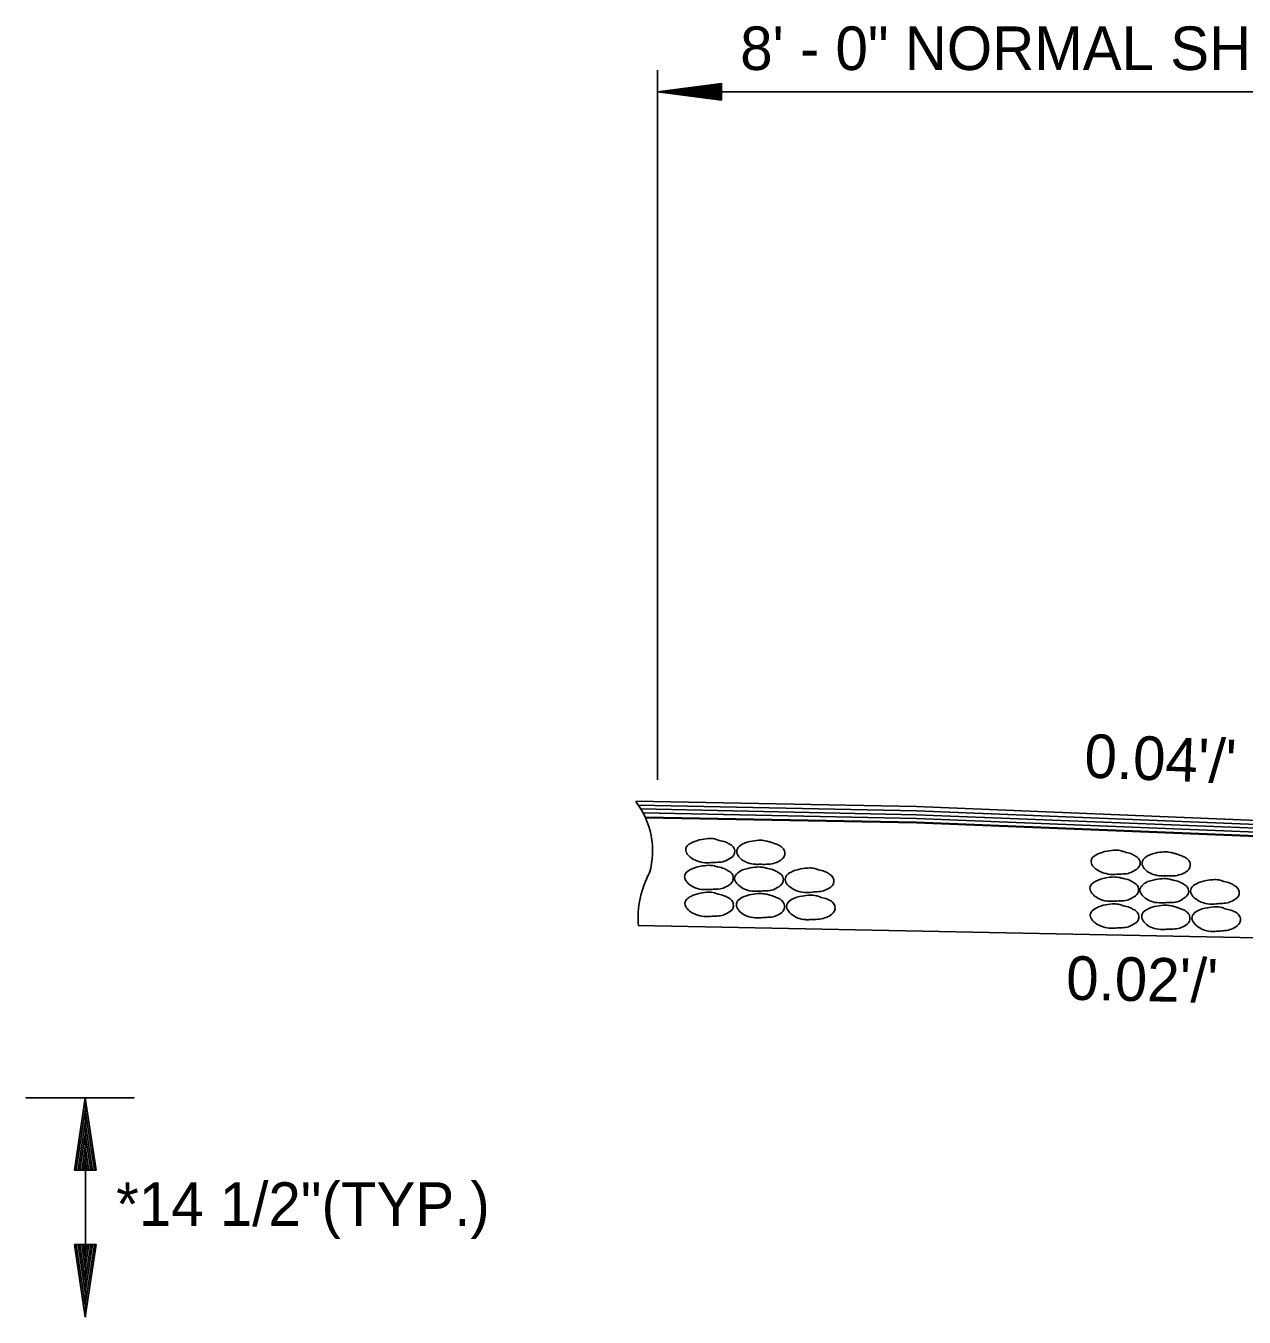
# Model space of a CAD drawing. Extents: x -2842 to 2681, y -2139 to 474.
# Drawn here: x 271.8 to 439.5, y -1517.8 to -1339.9 of the extents above; entities that cross this region are included whole.
import ezdxf

# ---------------------------------------------------------------- set-up
doc = ezdxf.new("R2010")
doc.units = 0
for name, color, linetype in [('BDR_Plan Profile Grid 3', 7, 'Continuous'), ('Default', 7, 'Continuous'), ('R_Border', 7, 'Continuous'), ('R_Border Notes', 7, 'Continuous')]:
    doc.layers.add(name, color=color, linetype=linetype)

msp = doc.modelspace()

# ---------------------------------------------------------------- linework, layer by layer
at = {"layer": 'BDR_Plan Profile Grid 3'}
for p, q in [((355.74, -1446.7), (394.39, -1447.45)), ((356.14, -1447.23), (394.39, -1448.03)), ((501.39, -1451.78), (394.39, -1447.45)), ((356.45, -1447.77), (394.39, -1448.57)), ((356.76, -1448.3), (394.39, -1449.1)), ((357.08, -1448.88), (394.39, -1449.59)), ((357.08, -1448.97), (394.39, -1449.68)), ((501.39, -1452.27), (394.39, -1448.03)), ((501.39, -1452.8), (394.39, -1448.57)), ((501.39, -1453.38), (394.39, -1449.1)), ((501.35, -1453.92), (394.35, -1449.59)), ((501.35, -1453.96), (394.39, -1449.68)), ((356.1, -1463.82), (640.63, -1469.52))]:
    msp.add_line(p, q, dxfattribs=at)
for centre, radius, start, end in [((347.05, -1453.52), 11.02, 343.9329, 37.9843), ((368.94, -1462.73), 12.87, 151.4224, 185.1058)]:
    msp.add_arc(centre, radius, start, end, dxfattribs=at)
for points in [[(366.04, -1451.82), (364.83, -1451.96), (363.5, -1452.4), (362.74, -1452.98), (362.65, -1453.43), (362.96, -1454.14), (363.36, -1454.5), (364.17, -1454.9), (365.28, -1455.17), (365.9, -1455.17), (366.8, -1455.12), (367.73, -1455.03), (368.49, -1454.72), (369.25, -1454.1), (369.38, -1453.65), (369.16, -1452.98), (368.62, -1452.58), (368.09, -1452.31), (367.24, -1452.09), (366.75, -1451.91), (366.04, -1451.82)], [(372.95, -1452.05), (371.79, -1452.18), (370.41, -1452.62), (369.74, -1453.25), (369.65, -1453.65), (369.96, -1454.36), (370.32, -1454.72), (371.16, -1455.17), (372.28, -1455.39), (372.86, -1455.39), (373.75, -1455.39), (374.73, -1455.26), (375.49, -1454.94), (376.2, -1454.27), (376.29, -1453.87), (376.07, -1453.25), (375.53, -1452.8), (375, -1452.58), (374.24, -1452.31), (373.71, -1452.18), (372.95, -1452.05)], [(421.86, -1453.43), (420.65, -1453.56), (419.31, -1454.01), (418.56, -1454.59), (418.47, -1455.03), (418.78, -1455.75), (419.18, -1456.1), (419.98, -1456.5), (421.1, -1456.77), (421.72, -1456.77), (422.61, -1456.73), (423.55, -1456.64), (424.31, -1456.33), (425.07, -1455.7), (425.2, -1455.26), (424.98, -1454.59), (424.44, -1454.19), (423.91, -1453.92), (423.06, -1453.69), (422.57, -1453.52), (421.86, -1453.43)], [(428.77, -1453.65), (427.61, -1453.78), (426.23, -1454.23), (425.56, -1454.85), (425.47, -1455.26), (425.78, -1455.97), (426.14, -1456.33), (426.98, -1456.77), (428.1, -1456.99), (428.68, -1456.99), (429.57, -1456.99), (430.55, -1456.86), (431.31, -1456.55), (432.02, -1455.88), (432.11, -1455.48), (431.89, -1454.85), (431.35, -1454.41), (430.82, -1454.19), (430.06, -1453.92), (429.52, -1453.78), (428.77, -1453.65)], [(365.81, -1455.52), (364.66, -1455.66), (363.27, -1456.1), (362.56, -1456.73), (362.47, -1457.08), (362.78, -1457.8), (363.18, -1458.2), (363.94, -1458.64), (365.1, -1458.87), (365.73, -1458.87), (366.62, -1458.82), (367.6, -1458.73), (368.36, -1458.38), (369.07, -1457.75), (369.16, -1457.31), (368.98, -1456.64), (368.4, -1456.24), (367.91, -1455.97), (367.06, -1455.75), (366.57, -1455.61), (365.81, -1455.52)], [(372.68, -1455.75), (371.52, -1455.88), (370.14, -1456.33), (369.47, -1456.95), (369.34, -1457.31), (369.65, -1458.02), (370.09, -1458.42), (370.85, -1458.87), (372.01, -1459.09), (372.59, -1459.09), (373.48, -1459.04), (374.46, -1458.96), (375.22, -1458.6), (375.94, -1457.97), (376.07, -1457.53), (375.85, -1456.86), (375.31, -1456.46), (374.78, -1456.19), (373.93, -1455.97), (373.44, -1455.83), (372.68, -1455.75)], [(379.68, -1455.88), (378.48, -1456.01), (377.14, -1456.46), (376.43, -1457.08), (376.34, -1457.48), (376.65, -1458.2), (377.05, -1458.55), (377.81, -1459), (378.97, -1459.27), (379.59, -1459.27), (380.48, -1459.18), (381.42, -1459.09), (382.18, -1458.78), (382.93, -1458.15), (383.02, -1457.71), (382.8, -1457.08), (382.27, -1456.64), (381.73, -1456.37), (380.93, -1456.15), (380.39, -1455.97), (379.68, -1455.88)], [(421.63, -1457.13), (420.47, -1457.26), (419.09, -1457.71), (418.38, -1458.33), (418.29, -1458.69), (418.6, -1459.4), (419, -1459.8), (419.76, -1460.25), (420.92, -1460.47), (421.54, -1460.47), (422.44, -1460.43), (423.42, -1460.34), (424.17, -1459.98), (424.89, -1459.36), (424.98, -1458.91), (424.8, -1458.24), (424.22, -1457.84), (423.73, -1457.57), (422.88, -1457.35), (422.39, -1457.22), (421.63, -1457.13)], [(428.5, -1457.35), (427.34, -1457.48), (425.96, -1457.93), (425.29, -1458.55), (425.16, -1458.91), (425.47, -1459.62), (425.91, -1460.03), (426.67, -1460.47), (427.83, -1460.69), (428.41, -1460.69), (429.3, -1460.65), (430.28, -1460.56), (431.04, -1460.2), (431.75, -1459.58), (431.89, -1459.13), (431.66, -1458.47), (431.13, -1458.06), (430.59, -1457.8), (429.75, -1457.57), (429.26, -1457.44), (428.5, -1457.35)], [(435.5, -1457.48), (434.29, -1457.62), (432.96, -1458.06), (432.24, -1458.69), (432.15, -1459.09), (432.47, -1459.8), (432.87, -1460.16), (433.63, -1460.61), (434.79, -1460.87), (435.41, -1460.87), (436.3, -1460.78), (437.24, -1460.69), (438, -1460.38), (438.75, -1459.76), (438.84, -1459.31), (438.62, -1458.69), (438.08, -1458.24), (437.55, -1457.97), (436.75, -1457.75), (436.21, -1457.57), (435.5, -1457.48)], [(365.81, -1459.22), (364.66, -1459.36), (363.32, -1459.8), (362.65, -1460.38), (362.52, -1460.83), (362.87, -1461.54), (363.23, -1461.9), (364.03, -1462.3), (365.15, -1462.57), (365.77, -1462.57), (366.66, -1462.52), (367.6, -1462.43), (368.36, -1462.12), (369.11, -1461.5), (369.2, -1461.05), (368.98, -1460.38), (368.45, -1459.98), (367.91, -1459.71), (367.11, -1459.49), (366.57, -1459.31), (365.81, -1459.22)], [(372.9, -1459.4), (371.7, -1459.54), (370.36, -1459.98), (369.69, -1460.56), (369.6, -1461.01), (369.92, -1461.72), (370.27, -1462.08), (371.08, -1462.52), (372.19, -1462.75), (372.81, -1462.75), (373.71, -1462.7), (374.64, -1462.61), (375.44, -1462.3), (376.16, -1461.63), (376.25, -1461.23), (376.02, -1460.56), (375.49, -1460.11), (374.95, -1459.89), (374.2, -1459.62), (373.66, -1459.49), (372.9, -1459.4)], [(379.81, -1459.62), (378.65, -1459.76), (377.27, -1460.2), (376.6, -1460.83), (376.51, -1461.23), (376.83, -1461.9), (377.23, -1462.3), (377.99, -1462.75), (379.15, -1463.01), (379.68, -1463.01), (380.57, -1462.97), (381.55, -1462.83), (382.36, -1462.52), (383.07, -1461.9), (383.2, -1461.41), (382.98, -1460.78), (382.44, -1460.34), (381.86, -1460.11), (381.11, -1459.89), (380.57, -1459.71), (379.81, -1459.62)], [(421.63, -1460.83), (420.47, -1460.96), (419.14, -1461.41), (418.47, -1461.99), (418.33, -1462.43), (418.69, -1463.15), (419.05, -1463.5), (419.85, -1463.9), (420.96, -1464.17), (421.59, -1464.17), (422.48, -1464.13), (423.42, -1464.04), (424.17, -1463.73), (424.93, -1463.1), (425.02, -1462.66), (424.8, -1461.99), (424.26, -1461.59), (423.73, -1461.32), (422.93, -1461.1), (422.39, -1460.92), (421.63, -1460.83)], [(428.72, -1461.01), (427.52, -1461.14), (426.18, -1461.59), (425.51, -1462.17), (425.42, -1462.61), (425.73, -1463.32), (426.09, -1463.68), (426.89, -1464.13), (428.01, -1464.35), (428.63, -1464.35), (429.52, -1464.31), (430.46, -1464.22), (431.26, -1463.9), (431.98, -1463.24), (432.07, -1462.83), (431.84, -1462.17), (431.31, -1461.72), (430.77, -1461.5), (430.01, -1461.23), (429.48, -1461.1), (428.72, -1461.01)], [(435.63, -1461.23), (434.47, -1461.36), (433.09, -1461.81), (432.42, -1462.43), (432.33, -1462.83), (432.65, -1463.5), (433.05, -1463.9), (433.8, -1464.35), (434.96, -1464.62), (435.5, -1464.62), (436.39, -1464.57), (437.37, -1464.44), (438.17, -1464.13), (438.89, -1463.5), (439.02, -1463.01), (438.8, -1462.39), (438.26, -1461.94), (437.68, -1461.72), (436.93, -1461.5), (436.39, -1461.32), (435.63, -1461.23)]]:
    msp.add_spline(points, degree=3, dxfattribs=at)
at = {"layer": 'Default'}
for p, q in [((271.75, -1487.54), (286.69, -1487.54)), ((278.44, -1497.53), (279.94, -1487.53)), ((281.44, -1497.53), (279.94, -1487.53)), ((279.95, -1487.54), (279.95, -1517.75)), ((278.69, -1497.53), (279.94, -1489.18)), ((281.19, -1497.53), (279.94, -1489.18)), ((278.96, -1497.53), (279.94, -1490.9)), ((280.94, -1497.53), (279.94, -1490.9)), ((279.21, -1497.53), (279.94, -1492.58)), ((280.69, -1497.53), (279.94, -1492.58)), ((279.46, -1497.53), (279.94, -1494.28)), ((280.44, -1497.53), (279.94, -1494.28)), ((279.71, -1497.53), (279.94, -1495.93)), ((280.19, -1497.53), (279.94, -1495.93)), ((278.44, -1497.53), (281.44, -1497.53)), ((278.44, -1507.75), (279.94, -1517.75)), ((281.44, -1507.75), (278.44, -1507.75)), ((278.69, -1507.75), (279.94, -1516.08)), ((278.96, -1507.75), (279.94, -1514.35)), ((279.21, -1507.75), (279.94, -1512.7)), ((279.46, -1507.75), (279.94, -1511)), ((279.71, -1507.75), (279.94, -1509.33)), ((281.44, -1507.75), (279.94, -1517.75)), ((280.44, -1507.75), (279.94, -1511)), ((280.94, -1507.75), (279.94, -1514.35)), ((281.19, -1507.75), (279.94, -1516.08)), ((280.69, -1507.75), (279.94, -1512.7)), ((280.19, -1507.75), (279.94, -1509.33))]:
    msp.add_line(p, q, dxfattribs=at)
at = {"layer": 'R_Border Notes'}
for p, q in [((358.73, -1443.75), (358.73, -1346.01)), ((367.55, -1347.86), (358.73, -1349.01)), ((367.55, -1347.86), (367.55, -1350.15)), ((358.73, -1349.01), (501.39, -1349.01)), ((358.73, -1349.01), (367.55, -1349.01)), ((367.55, -1350.15), (358.73, -1349.01)), ((367.55, -1348.78), (360.52, -1348.79)), ((367.55, -1349.23), (360.52, -1349.24)), ((367.55, -1348.56), (362.25, -1348.56)), ((367.56, -1349.47), (362.25, -1349.47)), ((367.54, -1348.32), (364.03, -1348.32)), ((367.55, -1349.7), (364.03, -1349.7)), ((367.55, -1348.09), (365.81, -1348.1)), ((367.55, -1349.93), (365.82, -1349.93))]:
    msp.add_line(p, q, dxfattribs=at)

# ---------------------------------------------------------------- texts
at = {"layer": 'Default'}
msp.add_text('*14 1/2"(TYP.)', height=6, dxfattribs=at).set_placement((284.19, -1505.18))
at = {"layer": 'R_Border'}
msp.add_text('8\' - 0" NORMAL SHOULDER', height=6, dxfattribs=at).set_placement((370.13, -1346.01))
for s, rotation, p in [("0.04'/'", 357.7094, (417.44, -1443.42)), ("0.02'/'", 358.8537, (414.97, -1474.02))]:
    msp.add_text(s, height=6, rotation=rotation, dxfattribs=at).set_placement(p)

doc.saveas('drawing.dxf')
